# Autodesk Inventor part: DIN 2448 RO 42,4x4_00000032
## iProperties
Created: 2006-02
Part Number: DIN 2448 RO 42,4x4_00000032
Material: Default
Document SubType Name: Modeling
Designer: FranzK
Stock Number: DIN 2448 RO 42,4x4
Mass: 2972.5 g
Surface Area: 14872.1 cm^2
Volume: 2972.5 cm^3
Density: 1 g/cm^3
G_L: 6160.000 mm
G_W: 42.400 mm
G_H: 42.400 mm
AFG_Item: 42.4 x 4
CSToolsMass: 3.0
CSToolsVolume: 2972500.0
CSToolsArea: 14872.0
Author: FranzK
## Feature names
1. AFG_Detailed_DIN 2448 RO 42,4x4_00000032 [Extrusion]
2. AFG_Simplified_DIN 2448 RO 42,4x4_00000032 [Extrusion]
